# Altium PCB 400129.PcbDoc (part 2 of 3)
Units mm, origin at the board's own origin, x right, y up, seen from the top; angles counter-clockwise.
Board outline 295.85 x 54.86 mm, 2 copper layers (Top Layer, Bottom Layer), stack 1.671 mm thick; 222 components, 127 nets, 693 pads, 1827 vias.
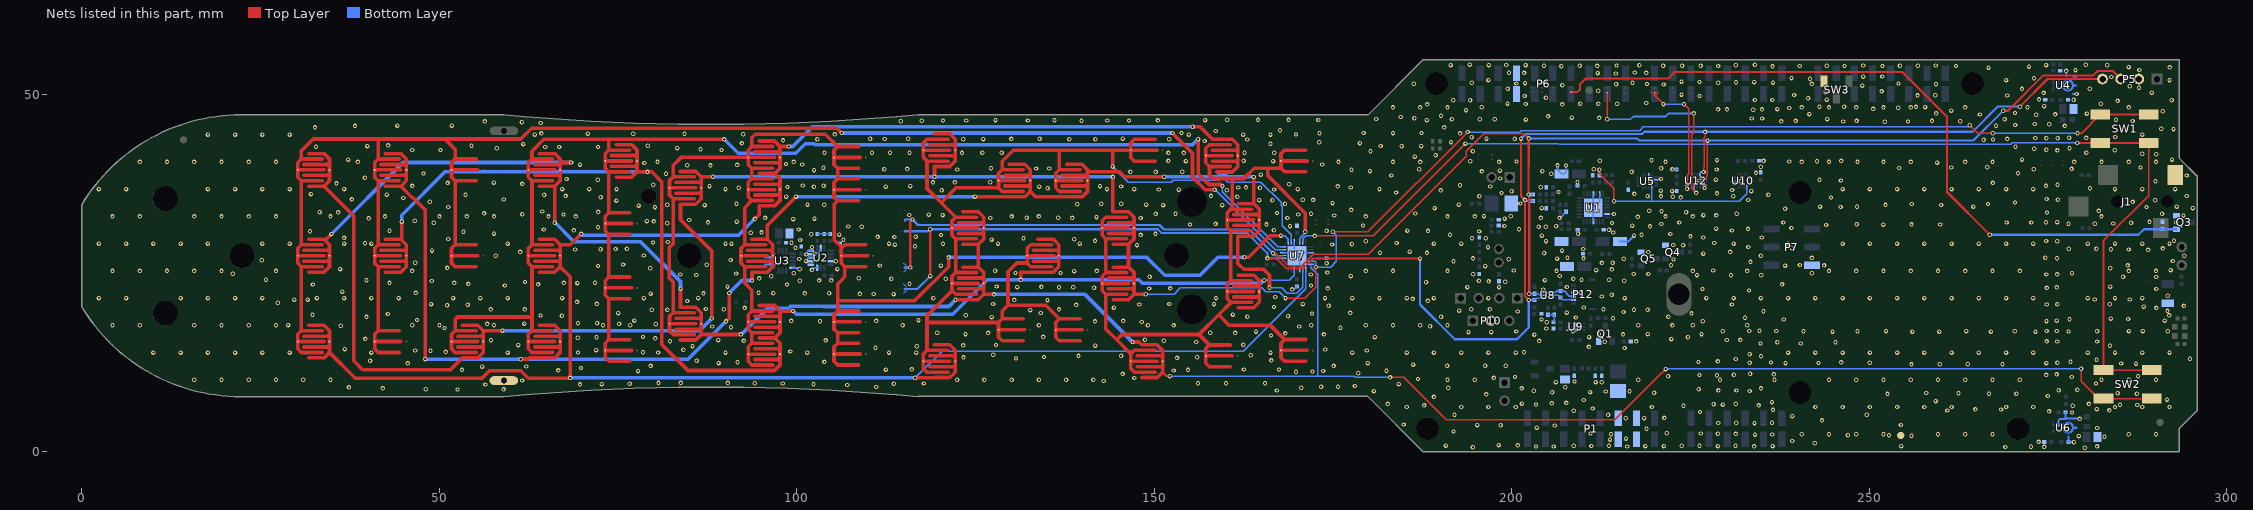
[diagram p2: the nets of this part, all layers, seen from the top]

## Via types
v1: diameter 0.61, hole 0.305, Top Layer to Bottom Layer, tented both sides, 1823 vias
v2: diameter 0.6, hole 0.3, Top Layer to Bottom Layer, tented both sides, 4 vias

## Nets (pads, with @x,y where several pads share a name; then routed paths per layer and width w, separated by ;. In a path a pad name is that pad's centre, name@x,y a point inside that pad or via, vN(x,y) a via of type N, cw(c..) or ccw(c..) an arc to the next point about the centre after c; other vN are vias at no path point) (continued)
D7: SB6.1 U12.13 | length 17.7
  Top Layer w0.203: SB6.1@219.96,50.252 219.96,50.077 219.96,49.885 v1(221.216,48.629) ; v1(224.079,48.606) 224.715,47.971 224.715,38.866 224.511,38.663 v1(224.511,36.805)
  Bottom Layer w0.203: v1(221.216,48.629) 221.239,48.606 v1(224.079,48.606) ; U12.13@224.491,37.305 224.511,37.284 v1(224.511,36.805)
D9: SB9.1 U12.11 | length 28.6
  Top Layer w0.203: v1(225.431,47.343) 225.431,44.663 225.161,44.393 225.161,36.84 v1(225.778,36.223)
  Top Layer w0.254: v1(213.346,46.517) SB9.1@213.346,50.252
  Bottom Layer w0.203: U12.11@225.516,37.08 225.516,36.486 v1(225.778,36.223)
  Bottom Layer w0.254: v1(213.346,46.517) 213.356,46.507 216.59,46.507 216.968,46.886 221.477,46.886 221.934,47.343 v1(225.431,47.343)
GND: Bat2.1 C1.2 C2.1 C3.1 C4.1 C5.1 C6.1 C7.2 C8.1 C9.1 C13.1 C14.1 C15.1 C18.1 C19.2 C20.2 C21.2 C22.2 C23.1 C24.1 C25.1 C26.1 C27.1 C28.1 C29.1 C30.1 C31.1 C32.1 C33.1 C34.1 C35.1 C36.1 C37.1 C39.1 C40.1 C41.1 C42.1 C43.1 C44.1 C45.1 C46.1 C47.1 C48.1 C50.1 C51.1 C52.1 C53.1 C54.1 C55.1 C56.1 J1.1 P1.6 P1.7 P5.2 P6.7 P7.6 P10.2 P12.3 Q1.2 Q3.2 Q4.2 Q5.2 R1.1 R8.1 R17.1 R31.1 R32.2 SW3.1 TP1.1 U1.4 U1.6 U1.13 U1.18 U1.29 U2.4 U2.8 U2.9 U2.10 U2.11 U2.12 U2.13 U2.15 U3.5 U3.10 U3.12 U4.5 U5.3 U5.6 U6.2 U6.5 U7.3 U7.10 U7.17 U7.26 U7.29 U8.4 U9.1 U9.7 U10.6 U12.6 | length 49.5
  Bottom Layer w0.203: U5.3@219.136,38.68 219.136,38.059 v1(219.352,37.844)
  Bottom Layer w0.229: v1(101.316,26.682) 101.316,26.785 101.672,27.141 U2.11@101.956,27.141 ; v1(101.346,27.602) 101.346,27.821 101.666,28.141 102.131,28.141 102.131,28.608 v1(102.138,28.614) ; v1@102.268,25.606 102.403,25.741 102.812,25.741 102.812,25.872 U2.8@102.856,25.916 ; v1(102.489,27.711) 102.489,27.721 102.592,27.824 103.029,27.824 103.356,28.152 U2.15@103.356,28.366 ; C34.1@102.856,30.485 C30.1@103.851,30.485 104.694,30.485 C31.1@104.697,30.483 ; U7.26@168.032,27.861 169.557,27.861 U7.29@169.957,27.461 ; v1(169.291,22.721) 169.551,22.721 C47.1@169.96,23.129 ; U7.29@169.557,28.011 U7.3@169.557,29.386 ; U7.17@170.357,25.536 170.357,27.061 U7.29@169.957,27.461 ; U7.10@171.882,27.861 170.357,27.861 U7.29@169.957,27.461 ; v1(204.394,22.714) 204.402,22.705 U8.4@204.402,22.316 ; C50.1@205.052,19.163 C51.1@205.955,19.163 205.955,18.244 C54.1@205.812,18.101 ; v1(206.381,40.069) 206.381,39.451 C19.2@206.941,38.891 207.351,38.891 207.583,39.124 v1(207.583,40.059) ; v1(206.684,32.722) 206.73,32.722 206.773,32.765 206.81,32.765 207.225,33.179 207.225,33.278 207.526,33.579 R8.1@207.577,33.579 ; U9.1@208.027,17.003 208.422,17.003 v1(208.559,16.866) 208.967,17.273 U9.7@208.967,17.503 ; P12.3@208.648,22.275 209.603,22.275 v1(209.607,22.271) ; v1(209.186,37.703) 209.188,37.701 209.188,37.694 209.187,37.693 C23.1@209.187,37.234 ; C27.1@209.212,31.083 209.212,30.567 v1(209.262,30.518) ; U1.18@211.4,32.234 U1.29@211.4,34.159 ; U1.4@211.4,36.084 U1.29@211.4,34.159 ; U1.6@212.3,36.084 212.3,35.059 v2(211.95,34.709) U1.29@211.4,34.159 ; 277.836,2.159 277.838,2.157 C42.1@277.838,1.388 277.87,1.355 v1(278.59,1.355)
  Bottom Layer w0.254: v1(226.198,37.941) 226.362,38.105 U12.6@226.941,38.105 ; U6.2@276.413,3.836 276.413,4.377 276.641,4.604 277.438,4.604 ; 277.524,52.478 v1(277.524,53.285) ; 278.463,50.038 v1@278.93,50.038 ; 278.463,52.472 278.994,52.472 278.999,52.476
  Bottom Layer w0.3: 95.545,27.221 U3.12@96.599,27.221 ; 95.58,26.221 U3.10@96.599,26.221 ; U3.5@99.399,25.721 100.247,25.721 v1(100.414,25.554) ; C20.2@215.114,29.433 216.26,29.433 v1(217.073,30.247) ; v1(219.352,37.844) 219.562,38.055 U5.6@220.161,38.055 ; v1(222.456,39.508) 222.459,39.505 C52.1@223.065,39.505 ; U10.6@231.049,37.705 231.834,37.705 v1(232.003,37.874) ; C45.1@277.438,5.533 277.438,4.604 277.444,4.597 277.503,4.656 279.111,4.656 ; U4.5@278.46,51.253 278.85,51.253 ; U6.5@278.463,3.386 278.943,3.386
  other v1: 280.121,0.591 194.551,0.638 269.012,0.679 274.444,0.702 272.607,0.713 203.378,0.747 205.842,0.747 216.129,0.747 233.904,0.772 281.838,0.772 218.669,0.803 221.259,0.803 228.813,0.803 236.467,0.803 254.465,0.803 211.125,0.823 208.661,0.849 213.589,0.849 223.768,0.849 226.232,0.853 231.27,0.849 190.778,0.877 200.838,0.905 198.148,0.943 242.37,1.219 273.66,1.396 239.217,1.524 213.734,1.724 215.954,1.86 282.872,2.117 279.273,2.207 255.89,2.263 252.735,2.321 246.99,2.337 234.01,2.413 236.423,2.43 213.869,2.459 240.539,2.459 244.349,2.459 248.159,2.459 251.969,2.459 259.589,2.459 263.399,2.459 267.209,2.459 286.259,2.459 290.069,2.459 231.307,2.515 228.813,2.54 211.008,2.565 226.416,2.565 221.668,2.619 191.844,2.849 218.83,3.247 281.873,3.347 203.475,3.402 205.991,3.687 198.434,3.719 195.153,3.745 254.407,3.761 184.861,3.835 233.934,4.022 228.875,4.039 231.369,4.064 236.372,4.064 243.364,4.409 279.416,4.611 215.925,4.708 218.506,4.723 221.331,4.756 239.214,5.006 191.99,5.192 213.459,5.198 249.631,5.195 278.336,5.519 226.31,5.589 275.137,5.66 208.648,5.747 260.912,5.793 283.556,5.81 236.518,5.872 268.422,5.929 264.822,5.943 281.788,5.979 211.298,6.075 185.294,6.269 192.914,6.269 196.724,6.269 200.534,6.269 219.584,6.269 242.444,6.269 246.254,6.269 250.064,6.269 253.874,6.269 257.684,6.269 261.494,6.269 269.114,6.269 272.924,6.269 284.354,6.269 288.164,6.269 291.974,6.269 278.441,6.446 223.995,6.457 187.731,6.499 234.512,6.511 287.452,6.553 285.039,6.589 229.514,6.613 203.378,6.633 228.219,6.671 182.637,6.709 231.307,6.725 280.693,6.709 201.404,6.755 205.588,6.787 207.625,6.849 236.372,6.965 259.257,7.096 210.053,7.257 291.617,7.315 189.103,7.696 274.959,7.808 196.424,8.037 252.527,8.107 266.725,8.128 270.561,8.128 287.401,8.137 262.458,8.198 284.709,8.201 257.962,8.243 219.898,8.279 205.631,8.35 210.947,8.362 213.131,8.443 216.446,8.47 180.709,8.504 233.249,8.516 203.065,8.561 167.144,8.594 228.882,8.598 231.401,8.581 276.456,8.614 279.086,8.682 52.564,8.73 48.113,8.756 59.004,8.746 226.12,8.756 42.108,8.881 201.361,8.881 234.851,8.881 191.11,8.961 170.56,8.964 37.371,9.02 207.467,9.053 111.121,9.078 173.33,9.119 175.692,9.119 178.048,9.22 107.052,9.349 56.464,9.42 69.698,9.445 102.352,9.46 72.72,9.476 184.18,9.485 76.624,9.535 113.589,9.535 98.055,9.566 117.784,9.561 281.686,9.566 94.117,9.612 156.108,9.612 160.02,9.612 165.481,9.612 80.661,9.655 83.775,9.655 90.358,9.655 212.573,9.745 206.145,9.759 211.709,9.764 208.763,9.84 142.926,9.916 61.595,9.994 15.749,10.079 19.559,10.079 23.369,10.079 27.179,10.079 30.989,10.079 34.799,10.079 122.429,10.079 126.239,10.079 130.049,10.079 133.859,10.079 137.669,10.079 141.479,10.079 191.009,10.079 194.819,10.079 217.679,10.079 229.109,10.079 236.729,10.079 244.349,10.079 248.159,10.079 251.969,10.079 255.779,10.079 259.589,10.079 263.399,10.079 267.209,10.079 271.019,10.079 282.449,10.079 286.259,10.079 290.069,10.079 186.868,10.2 147.222,10.33 197.488,10.356 200.45,10.465 278.303,10.465 221.851,10.583 287.553,10.566 228.697,10.728 226.241,10.744 274.729,10.775 231.051,10.791 276.187,10.839 236.636,10.845 145.567,10.903 233.315,10.931 178.511,11.006 169.816,11.201 172.131,11.236 77.811,11.292 173.609,11.307 182.474,11.354 66.672,11.396 152.705,11.39 53.188,11.467 154.711,11.467 112.471,11.505 162.535,11.517 167.445,11.517 116.095,11.542 69.825,11.734 56.015,11.929 62.186,11.938 79.561,12.025 175.082,12.025 190.95,12.052 196.262,12.052 199.157,12.052 186.195,12.2 255.88,12.243 259.842,12.268 263.754,12.268 268.605,12.268 285.198,12.362 287.274,12.35 45.593,12.378 238.275,12.411 89.078,12.422 179.85,12.416 242.888,12.429 274.749,12.422 233.249,12.463 250.038,12.471 276.29,12.471 236.248,12.505 91.719,12.534 246.075,12.522 103.871,12.583 226.097,12.574 278.114,12.601 228.813,12.652 40.335,12.742 86.004,12.736 166.374,12.793 281.762,12.878 231.307,12.996 294.827,13.029 130.658,13.066 153.187,13.142 123.317,13.218 156.007,13.237 134.569,13.269 234.84,13.374 139.395,13.422 145.357,13.447 163.5,13.523 127.483,13.574 233.249,13.65 10.034,13.889 13.844,13.889 17.654,13.889 21.464,13.889 25.274,13.889 29.084,13.889 40.514,13.889 59.564,13.889 69.41,13.908 80.619,13.908 90.044,13.889 101.474,13.889 112.904,13.889 116.714,13.889 166.244,13.889 177.674,13.889 185.294,13.889 189.104,13.889 192.914,13.889 196.724,13.889 200.534,13.889 238.634,13.889 242.444,13.889 246.254,13.889 250.064,13.889 253.874,13.889 257.684,13.889 261.494,13.889 265.304,13.889 269.114,13.889 272.924,13.889 280.544,13.889 284.354,13.889 288.164,13.889 291.974,13.889 78.511,13.932 201.708,13.946 50.927,13.987 99.111,14.031 48.793,14.133 46.66,14.184 179.705,14.184 71.958,14.234 84.15,14.294 173.912,14.322 36.805,14.379 215.765,14.537 111.019,14.565 210.773,14.688 116.781,14.768 85.419,14.797 283.637,14.839 141.732,14.863 123.292,14.893 61.063,14.935 127.867,14.956 162.458,14.983 234.78,15.164 240.4,15.164 237.135,15.33 245.263,15.329 155.88,15.367 212.98,15.415 276.276,15.432 281.838,15.432 217.392,15.459 274.787,15.457 82.271,15.479 92.608,15.525 203.829,15.525 151.331,15.555 57.252,15.606 104.034,15.594 89.027,15.631 230.062,15.65 231.962,15.661 148.683,15.684 222.315,15.775 39.675,15.809 80.209,15.88 69.369,15.96 72.006,16.032 224.612,16.039 78.495,16.066 180.819,16.055 210.8,16.053 134.468,16.089 166.319,16.277 203.156,16.405 173.721,16.434 212.189,16.448 215.534,16.434 123.596,16.47 219.013,16.47 226.517,16.47 168.334,16.577 126.771,16.647 161.315,16.647 119.659,16.673 157.836,16.673 193.948,16.755 197.113,16.755 164.228,16.817 244.838,16.815 256.007,16.815 259.791,16.815 266.991,16.815 273.221,16.817 200.636,16.84 277.838,16.84 229.505,16.87 240.792,16.866 248.336,16.866 270.332,16.87 281.838,16.866 291.719,16.87 233.211,16.898 236.982,16.898 252.324,16.891 263.55,16.891 274.787,16.898 276.191,16.898 286.289,16.891 288.215,16.891 234.634,16.934 204.82,17.249 50.749,17.333 176.033,17.362 90.805,17.42 88.187,17.533 170.262,17.539 188.57,17.567 36.227,17.636 152.705,17.689 222.456,17.689 4.319,17.699 8.129,17.699 15.749,17.699 19.559,17.699 23.369,17.699 27.179,17.699 46.229,17.699 50.039,17.699 57.659,17.699 72.899,17.699 76.709,17.699 114.809,17.699 133.859,17.699 149.099,17.699 171.959,17.699 179.579,17.699 183.389,17.699 187.199,17.699 191.009,17.699 217.679,17.699 225.299,17.699 232.919,17.699 28.88,17.729 80.273,17.861 56.714,17.907 61.917,17.937 75.162,17.932 69.41,17.983 72.085,17.983 204.88,18.142 148.238,18.171 141.707,18.248 103.257,18.262 226.695,18.263 274.764,18.294 99.238,18.324 111.123,18.324 145.667,18.326 77.292,18.365 276.207,18.364 291.313,18.364 117.023,18.425 46.888,18.445 204.14,18.517 238.032,18.517 277.978,18.562 286.182,18.593 283.743,18.644 214.151,18.68 232.609,18.76 208.955,18.787 127.271,18.851 39.827,18.876 163.017,18.908 190.103,18.898 221.885,18.908 168.719,18.965 67.158,19.035 64.16,19.069 291.941,19.089 123.622,19.107 32.283,19.17 160.985,19.198 42.824,19.286 172.059,19.355 225.131,19.371 75.032,19.405 134.112,19.432 177.409,19.435 207.671,19.477 215.629,19.563 200.838,19.634 235.196,19.656 291.687,19.725 192.634,19.752 132.653,19.824 79.733,19.873 81.907,19.873 218.983,19.88 217.073,19.888 57.201,19.924 61.976,19.924 136.677,19.932 194.335,19.958 196.926,19.945 212.824,19.945 89.786,19.961 87.299,19.985 92.705,20.137 290.129,20.142 144.348,20.178 210.059,20.185 166.731,20.254 288.373,20.32 293.98,20.422 174.372,20.448 51.105,20.508 139.09,20.559 53.975,20.584 147.902,20.619 230.768,20.621 274.803,20.621 48.87,20.666 158.344,20.661 170.753,20.666 276.283,20.65 283.616,20.65 72.028,20.693 127.457,20.686 152.11,20.692 27.432,20.853 69.285,20.984 84.675,21.098 188.252,21.117 135.07,21.221 130.423,21.254 29.722,21.295 31.598,21.295 281.508,21.311 286.397,21.311 186.125,21.395 119.109,21.485 2.414,21.509 6.224,21.509 13.844,21.509 17.654,21.509 21.464,21.509 25.274,21.509 32.894,21.509 36.704,21.509 40.514,21.509 44.324,21.509 51.944,21.509 55.754,21.509 59.564,21.509 67.184,21.509 78.614,21.509 86.234,21.509 158.624,21.509 173.864,21.509 177.674,21.509 181.484,21.509 185.294,21.509 189.104,21.509 196.724,21.509 215.774,21.509 227.204,21.509 231.014,21.509 234.824,21.509 238.634,21.509 242.444,21.509 246.254,21.509 250.064,21.509 253.874,21.509 257.684,21.509 261.494,21.509 265.304,21.509 269.114,21.509 272.924,21.509 280.544,21.509 284.354,21.509 288.164,21.509 166.915,21.663 212.582,21.735 291.718,21.832 213.957,21.977 110.757,22.077 113.553,22.067 108.804,22.098 79.564,22.134 86.97,22.17 96.735,22.193 101.128,22.17 104.522,22.193 46.711,22.235 94.66,22.266 36.449,22.413 233.166,22.573 226.656,22.784 290.128,22.784 149.276,22.845 152.253,22.87 174.255,22.87 274.816,22.932 141.58,22.963 136.677,23.023 138.659,23.023 276.19,23.007 130.835,23.049 193.779,23.049 198.194,23.038 207.695,23.052 134.214,23.074 90.313,23.11 127.949,23.124 283.675,23.11 59.192,23.266 171.915,23.275 32.334,23.404 63.83,23.429 98.646,23.414 237.8,23.429 54.077,23.492 115.763,23.512 69.328,23.607 43.053,23.633 52.095,23.633 67.412,23.632 71.78,23.658 188.01,23.721 62.001,23.759 199.086,23.8 196.749,23.851 48.958,23.904 100.428,23.942 195.394,23.942 215.727,23.945 103.129,23.981 104.816,23.981 39.827,24.013 204.616,24.018 209.739,24.062 213.625,24.065 25.781,24.079 113.236,24.223 120.834,24.215 208.607,24.217 94.755,24.27 108.676,24.281 290.107,24.46 149.351,24.502 285.482,24.491 96.444,24.561 177.461,24.58 206.696,24.597 230.656,24.699 234.89,24.7 225.897,24.723 85.954,24.74 83.718,24.816 171.867,24.815 274.749,24.811 276.27,24.828 194.615,24.848 217.048,24.873 219.099,24.873 21.132,24.906 91.528,24.953 99.574,24.974 241.927,24.975 278.327,24.975 136.89,25.01 130.591,25.022 174.211,25.081 138.811,25.275 141.961,25.309 4.319,25.319 8.129,25.319 11.939,25.319 15.749,25.319 19.559,25.319 27.179,25.319 46.229,25.319 127.737,25.337 179.579,25.319 183.389,25.319 191.009,25.319 206.249,25.319 225.299,25.319 232.919,25.319 244.349,25.319 248.159,25.319 251.969,25.319 255.779,25.319 259.589,25.319 263.399,25.319 267.209,25.319 271.019,25.319 286.259,25.319 290.069,25.319 228.177,25.36 200.269,25.375 211.799,25.42 292.125,25.421 102.115,25.453 213.982,25.526 36.144,25.563 105.68,25.56 79.505,25.69 283.691,25.69 51.14,25.733 196.291,25.975 72.212,25.995 120.138,26.05 238.214,26.046 111.633,26.067 243.666,26.08 286.106,26.08 222.252,26.09 240.28,26.144 87.427,26.162 75.717,26.198 174.092,26.391 212.597,26.432 46.66,26.457 214.089,26.452 233.367,26.571 105.461,26.67 191.844,26.67 292.434,26.7 25.195,26.805 90.752,26.838 169.407,26.911 170.507,26.911 222.605,26.904 199.571,26.95 100.355,26.971 215.656,27.012 206.33,27.028 194.564,27.064 210.024,27.059 276.24,27.082 241.927,27.131 274.604,27.143 207.789,27.157 57.912,27.432 234.823,27.432 294.027,27.432 78.614,27.461 226.788,27.734 204.507,27.784 188.127,27.834 181.56,27.861 219.086,27.951 61.341,27.976 230.533,27.976 169.407,28.011 170.507,28.011 185.719,28.011 48.997,28.154 207.012,28.142 289.001,28.245 69.037,28.297 286.25,28.296 72.568,28.331 74.672,28.366 283.784,28.346 209.973,28.37 76.251,28.408 277.874,28.397 281.748,28.397 291.036,28.464 239.152,28.499 99.824,28.546 196.672,28.643 233.074,28.661 116.544,28.758 223.947,28.895 147.574,28.911 222.564,28.939 113.71,28.991 174.866,29.005 177.628,29.045 120.447,29.102 2.414,29.129 6.224,29.129 10.034,29.129 13.844,29.129 17.654,29.129 25.274,29.129 29.084,29.129 36.704,29.129 40.514,29.129 59.564,29.129 90.044,29.129 90.881,29.128 112.904,29.129 128.144,29.129 139.574,29.129 189.104,29.129 192.914,29.129 231.014,29.129 238.634,29.129 246.254,29.129 250.064,29.129 253.874,29.129 257.684,29.129 261.494,29.129 265.304,29.129 269.114,29.129 272.924,29.129 280.544,29.129 284.354,29.129 288.164,29.129 291.974,29.129 39.624,29.167 183.888,29.221 228.306,29.208 99.276,29.258 79.897,29.288 81.966,29.347 179.563,29.457 276.265,29.457 204.778,29.481 274.717,29.496 141.707,29.513 292.599,29.538 100.47,29.627 106.536,29.678 127.25,29.69 138.811,29.73 51.257,29.779 131.705,29.88 194.437,29.866 196.342,29.87 36.703,29.932 226.776,29.986 234.953,29.986 113.649,30.059 111.304,30.072 116.628,30.096 224.977,30.137 204.174,30.247 120.174,30.333 148.084,30.349 218.124,30.355 105.94,30.389 191.354,30.378 102.022,30.44 150.17,30.485 222.17,30.477 57.658,30.529 93.574,30.643 95.074,30.693 214.173,30.68 53.391,30.784 195.428,30.821 31.928,30.846 43.053,30.917 174.092,30.917 188.276,30.908 185.391,30.945 68.811,30.973 230.768,30.958 166.728,30.998 213.608,31.064 64.643,31.097 100.258,31.1 200.998,31.139 233.031,31.183 228.578,31.228 239.09,31.318 72.217,31.405 109.093,31.483 203.744,31.483 204.751,31.483 107.198,31.519 219.316,31.531 206.188,31.559 168.986,31.576 198.956,31.589 179.188,31.66 216.835,31.646 243.942,31.725 251.943,31.785 154.986,31.798 165.684,31.817 255.89,31.817 259.918,31.801 248.209,31.829 158.58,31.884 220.9,31.873 277.851,31.902 281.508,31.899 284.103,31.932 81.89,31.987 213.998,32.008 49.251,32.04 286.595,32.037 87.584,32.1 223.423,32.075 237.967,32.08 269.193,32.08 272.656,32.075 274.69,32.109 276.276,32.131 292.917,32.131 289.173,32.166 91.599,32.205 80.025,32.241 79.017,32.273 46.584,32.319 84.975,32.423 99.517,32.548 102.483,32.624 198.984,32.624 40.157,32.649 127.061,32.708 148.084,32.702 168.614,32.708 95.58,32.729 136.569,32.732 138.539,32.727 204.03,32.729 132.152,32.747 141.927,32.836 217.606,32.867 4.319,32.939 8.129,32.939 15.749,32.939 19.559,32.939 23.369,32.939 27.179,32.939 34.799,32.939 42.419,32.939 50.039,32.939 53.849,32.939 57.659,32.939 65.279,32.939 69.089,32.939 130.049,32.939 133.859,32.939 179.579,32.939 191.009,32.939 194.819,32.939 199.852,32.944 221.489,32.939 225.299,32.939 282.449,32.939 196.105,32.976 175.156,33.061 293.915,33.043 228.6,33.075 120.405,33.113 226.788,33.111 115.73,33.124 118.469,33.18 170.126,33.189 67.392,33.203 61.634,33.234 214.272,33.259 150.19,33.313 152.972,33.312 171.909,33.313 231.46,33.313 290.94,33.312 56.286,33.355 186.485,33.347 167.157,33.407 35.89,33.488 274.838,33.484 33.274,33.513 224.366,33.524 72.241,33.56 64.423,33.613 220.935,33.655 282.07,33.706 219.218,33.726 177.547,33.84 238.209,33.998 189.198,34.094 204.174,34.091 295.216,34.091 80.18,34.224 51.257,34.243 245.975,34.245 288.743,34.245 248.274,34.281 243.103,34.296 264.536,34.298 292.974,34.298 77.892,34.443 87.122,34.515 151.238,34.515 159.512,34.515 260.033,34.524 81.889,34.549 103.851,34.549 252.243,34.549 101.496,34.577 148.869,34.579 192.569,34.577 139.22,34.644 255.919,34.67 266.582,34.67 91.567,34.707 142.575,34.713 145.372,34.709 168.267,34.714 201.193,34.729 174.911,34.789 270.366,34.874 286.813,34.963 48.692,34.986 74.779,35.139 166.512,35.18 289.975,35.188 164.68,35.209 233.052,35.222 172.204,35.239 170.753,35.251 276.355,35.269 59.036,35.29 37.795,35.316 274.777,35.374 44.982,35.509 244.636,35.574 72.568,35.6 223.632,35.595 161.62,35.672 222.511,35.677 98.522,35.693 220.85,35.732 195.459,35.753 218.983,35.753 230.952,35.756 294.382,35.778 67.68,35.796 157.937,35.799 53.67,35.951 42.672,35.977 64.668,35.966 235.873,35.966 32.055,36.053 217.142,36.082 228.697,36.152 198.555,36.208 183.819,36.271 206.531,36.338 199.974,36.449 233.477,36.463 222.414,36.47 220.828,36.535 190.052,36.575 120.258,36.597 160.124,36.597 230.801,36.632 150.622,36.688 153.425,36.673 166.755,36.688 2.414,36.749 6.224,36.749 17.654,36.749 21.464,36.749 25.274,36.749 29.084,36.749 36.704,36.749 67.184,36.749 70.994,36.749 74.804,36.749 90.044,36.749 143.384,36.749 147.194,36.749 170.054,36.749 181.484,36.749 246.254,36.749 250.064,36.749 253.874,36.749 257.684,36.749 261.494,36.749 265.304,36.749 269.114,36.749 272.924,36.749 284.354,36.749 288.164,36.749 292.78,36.751 135.077,36.866 280.849,36.864 91.884,36.932 164.77,36.932 161.738,36.97 177.479,36.972 162.829,36.992 204.045,37.019 98.704,37.044 102.403,37.087 112.441,37.096 133.909,37.094 145.364,37.117 196.97,37.113 175.652,37.134 87.804,37.171 115.878,37.171 142.409,37.171 46.253,37.196 274.69,37.196 103.759,37.221 100.838,37.247 192.754,37.285 79.942,37.348 276.309,37.368 168.885,37.419 61.634,37.475 35.636,37.552 51.181,37.621 267.264,37.621 57.633,37.653 119.059,37.685 122.084,37.694 127.051,37.711 290.012,37.86 246.016,37.951 72.183,38.06 243.019,38.055 228.52,38.074 67.818,38.161 220.848,38.161 198.376,38.224 39.611,38.35 294.362,38.65 183.155,38.657 164.897,38.771 81.714,38.898 205.522,38.898 47.803,38.924 270.79,38.964 234.152,39.022 146.66,39.177 216.746,39.173 150.19,39.188 153.899,39.188 195.814,39.229 204.274,39.255 180.167,39.268 198.305,39.335 102.412,39.403 177.584,39.452 122.449,39.485 228.64,39.485 112.256,39.514 187.061,39.532 211.445,39.521 272.986,39.524 115.448,39.573 278.273,39.573 133.477,39.634 135.306,39.634 127.169,39.659 220.877,39.66 254.178,39.7 103.737,39.73 261.442,39.776 287.917,39.779 266.485,39.815 234.814,39.876 87.935,40.066 84.684,40.079 91.669,40.142 69.698,40.174 100.779,40.193 173.494,40.193 98.501,40.257 78.7,40.396 259.472,40.455 248.336,40.55 8.129,40.559 11.939,40.559 15.749,40.559 19.559,40.559 23.369,40.559 27.179,40.559 38.609,40.559 80.519,40.559 99.569,40.559 175.769,40.559 183.389,40.559 187.199,40.559 198.22,40.561 221.489,40.559 240.539,40.559 244.349,40.559 251.969,40.559 255.779,40.559 263.399,40.559 267.209,40.559 278.639,40.559 282.449,40.559 286.259,40.559 290.069,40.559 238.782,40.607 194.193,40.633 200.66,40.615 242.667,40.633 166.613,40.658 154.42,40.666 151.972,40.7 235.214,40.7 246.075,40.698 162.49,40.72 212.297,40.719 219.529,40.789 228.681,40.797 37.287,40.879 271.34,40.869 292.307,40.869 186.428,41.288 189.339,41.476 290.107,41.631 288.163,41.699 103.879,41.823 110.531,41.826 113.036,41.824 115.763,41.823 123.115,41.819 151.967,41.819 154.122,41.819 162.623,41.824 166.765,41.826 125.954,41.833 128.645,41.833 280.349,41.845 180.226,42.049 194.551,42.054 276.29,42.159 284.307,42.182 46.228,42.227 50.19,42.215 89.484,42.227 274.749,42.251 86.546,42.33 273.041,42.381 58.039,42.454 83.297,42.479 277.984,42.47 64.829,42.632 66.777,42.632 72.212,42.632 270.44,42.666 32.766,42.682 184.59,42.741 39.954,42.759 187.33,42.759 181.653,42.782 54.525,42.809 79.173,42.809 42.875,42.86 61.773,43.038 166.243,43.104 92.329,43.14 178.748,43.18 173.067,43.309 191.495,43.316 157.034,43.481 98.086,43.561 265.973,43.65 267.287,43.676 163.007,43.687 102.887,43.731 123.292,43.731 138.125,43.716 141.757,43.717 152.094,43.718 126.086,43.739 110.261,43.779 112.319,43.764 130.021,43.775 269.277,43.775 115.595,43.79 133.96,43.785 200.391,43.79 145.593,43.815 196.459,43.81 274.749,43.872 276.316,43.872 273.186,43.891 277.928,43.922 280.332,43.913 194.376,43.99 284.378,44.044 17.654,44.369 21.464,44.369 25.274,44.369 29.084,44.369 63.374,44.369 154.814,44.369 162.434,44.369 166.244,44.369 169.816,44.385 288.164,44.369 92.514,44.41 105.32,44.399 77.149,44.486 84.308,44.486 70.775,44.511 64.287,44.537 192.794,44.544 173.11,44.568 153.809,44.587 183.389,44.581 187.37,44.587 179.272,44.601 158.593,44.867 167.582,44.982 292.52,45.134 290.82,45.179 32.629,45.384 190.539,45.385 38.22,45.592 267.697,45.604 277.333,45.592 44.16,45.627 51.766,45.627 270.383,45.706 275.159,45.808 273.127,45.858 64.211,45.984 61.57,46.086 252.138,46.161 56.366,46.214 237.676,46.218 246.334,46.201 255.407,46.203 114.554,46.246 262.709,46.229 239.679,46.285 248.209,46.286 258.751,46.29 286.806,46.279 117.481,46.319 139.811,46.319 120.447,46.34 123.697,46.336 132.328,46.335 143.424,46.34 146.463,46.335 136.045,46.373 150.504,46.358 157.103,46.394 127.787,46.4 164.506,46.423 168.767,46.423 172.945,46.408 188.098,46.402 160.201,46.444 201.966,46.471 284.48,46.452 191.618,46.513 195.516,46.517 197.619,46.517 268.91,46.513 181.047,46.551 244.096,46.535 233.553,46.621 234.998,46.621 186.377,46.645 212.216,46.708 208.379,46.744 184.468,46.839 205.078,46.922 190.086,47.016 273.33,47.155 265.449,47.18 275.975,47.201 241.605,47.23 280.415,47.31 259.359,47.343 270.353,47.396 291.029,47.633 261.442,47.72 193.58,47.796 233.757,47.841 228.844,47.903 230.093,47.903 234.981,47.903 237.135,47.936 250.546,47.968 238.793,48.087 254.025,48.121 183.389,48.179 187.199,48.179 191.009,48.179 195.801,48.188 240.539,48.179 244.349,48.179 248.159,48.179 251.969,48.179 255.779,48.179 263.399,48.179 272.109,48.188 286.259,48.179 257.788,48.22 256.515,48.243 243.019,48.263 246.463,48.278 274.444,48.351 188.177,48.591 207.043,48.594 201.927,48.658 214.738,48.673 282.365,48.678 199.388,48.701 209.589,48.689 212.105,48.696 218.806,48.781 284.709,49.084 191.813,49.167 194.168,49.186 292.265,49.171 233.987,49.216 236.436,49.216 244.031,49.264 278.562,49.255 273.721,49.292 241.43,49.458 204.762,49.523 201.791,49.775 226.241,49.764 256.728,49.853 269.265,49.845 259.211,49.871 239.467,49.901 223.721,49.958 278.974,50.049 274.359,50.203 289.484,50.241 243.792,50.313 246.569,50.364 251.714,50.416 212.085,50.505 271.348,50.769 199.412,50.785 280.816,50.791 287.705,50.935 286.397,51.132 248.993,51.22 207.068,51.277 221.226,51.387 214.581,51.414 259.311,51.414 218.898,51.448 241.943,51.468 186.279,51.492 200.635,51.521 254.069,51.508 201.848,51.567 194.399,51.619 216.882,51.624 228.854,51.624 236.518,51.638 231.343,51.697 204.603,51.726 226.241,51.726 233.904,51.715 223.727,51.776 196.724,51.989 269.114,51.989 291.974,51.989 241.693,52.172 273.009,52.263 239.099,52.273 283.82,52.432 249.149,52.476 251.816,52.502 214.542,52.916 211.989,52.968 201.721,52.998 218.786,52.998 199.608,53.019 217.192,53.055 278.83,53.386 287.759,53.412 266.653,53.742 292.014,53.766 286.25,53.809 272.313,53.884 236.447,53.914 206.934,53.935 228.848,53.96 240.253,53.962 246.517,53.96 251.825,53.967 262.119,53.96 204.495,53.994 211.938,53.985 221.158,53.994 226.394,53.989 254.264,53.993 256.773,53.993 209.474,54.011 223.808,54.011 244.031,54.005 214.63,54.036 249.141,54.039 259.272,54.039 217.83,54.062 231.307,54.062 191.44,54.087 196.774,54.087 201.93,54.087 274.713,54.087 283.261,54.077 199.212,54.112 233.985,54.135 280.264,54.135 194.107,54.155
  other v2: 210.85,33.609 211.95,33.609 210.85,34.709
I2C_CLK: P5.3 R13.1 R28.2 SB19.2 SB20.2 U7.25 U8.3 U12.8 | length 226.8
  Top Layer w0.203: v1(226.941,36.896) 226.941,38.204 227.354,38.618 v1(227.355,43.536) v1(227.355,43.536)
  Top Layer w0.254: v1(166.593,27.789) 167.01,27.789 168.767,26.032 170.609,26.032 172.217,27.64 179.921,27.64 193.63,41.349 193.63,42.013 196.095,44.478 201.722,44.478 v1(202.356,43.843)
  Top Layer w0.305: v1(115.878,25.791) 115.878,32.188 v1(116.184,32.494) ; v1(202.356,43.843) v1(202.34,35.993) 202.439,36.095 v1(202.439,22.105) ; v1(268.708,47.706) 269.381,47.706 274.325,52.65 281.306,52.65 281.915,53.26 284.023,53.26 P5.3@285.143,52.14
  Bottom Layer w0.203: v1(166.593,27.789) 166.918,27.463 168.031,27.463 U7.25@168.032,27.461 ; v1(202.439,22.105) 202.366,22.105 202.361,22.11 R28.2@203.156,22.11 203.688,22.11 203.881,21.916 U8.3@204.402,21.916 ; v1(226.941,36.896) U12.8@226.941,37.305
  Bottom Layer w0.305: SB19.2@115.087,25.775 115.375,25.775 115.862,25.775 v1(115.878,25.791) ; 115.138,32.493 v1@116.185,32.493 ; v1(116.184,32.494) v1@116.185,32.493 ; v1(166.593,27.789) 163.291,31.091 151.349,31.091 150.718,31.721 116.956,31.721 v1@116.185,32.493 ; v1(202.34,35.993) R13.1@202.909,35.993 ; v1(202.356,43.843) 217.523,43.843 217.832,43.534 264.536,43.534 v1(268.708,47.706)
I2C_CLK_TP: P12.4 R30.2 U8.6 | length 3.3
  Bottom Layer w0.203: U8.6@205.702,22.316 206.157,22.316 206.342,22.501 R30.2@206.829,22.501 207.322,22.501 208.048,21.775 P12.4@208.648,21.775
I2C_DATA: P5.4 R11.1 R27.2 SB21.2 SB24.2 U7.24 U8.2 U12.4 | length 234.4
  Top Layer w0.203: v1(226.821,39.143) 226.821,39.807 226.907,39.893 226.907,43.23 226.822,43.315 226.822,43.872 227.026,44.077 v1(227.026,44.748)
  Top Layer w0.254: v1(165.815,27.059) 167.071,27.059 168.503,25.628 170.744,25.628 172.15,27.034 v1(187.155,27.034)
  Top Layer w0.305: v1(118.671,24.58) v1(118.671,31.137) ; v1(201.287,43.815) 201.287,35.78 v1(201.82,35.247) 201.842,35.225 201.842,21.758 v1(202.358,21.241) ; v1(271.033,48.275) 274.898,52.14 P5.4@282.603,52.14
  Bottom Layer w0.203: v1(165.815,27.059) 167.508,27.059 167.511,27.061 U7.24@168.032,27.061 ; R27.2@203.156,21.241 203.431,21.516 U8.2@204.402,21.516 ; U12.4@226.316,38.747 226.316,38.944 226.515,39.143 v1(226.821,39.143)
  Bottom Layer w0.305: SB24.2@115.087,22.795 116.886,22.795 v1(118.671,24.58) ; SB21.2@115.11,30.846 118.376,30.846 118.671,31.142 150.484,31.142 151.036,30.59 163.001,30.59 165.815,27.776 v1(165.815,27.059) ; v1(187.155,27.034) 187.155,20.603 192.003,15.755 200.727,15.755 202.358,17.387 v1(202.358,21.241) R27.2@203.156,21.241 ; v1(201.287,43.815) 201.927,44.455 218.218,44.455 218.535,44.772 264.44,44.772 267.959,48.29 271.018,48.29 v1(271.033,48.275) ; v1(201.82,35.247) 201.978,35.089 R11.1@202.925,35.089
I2C_DATA_TP: P12.5 R29.2 U8.7 | length 3.2
  Bottom Layer w0.203: U8.7@205.702,21.916 206.506,21.916 R29.2@206.827,21.596
  Bottom Layer w0.254: R29.2@206.827,21.596 207.147,21.275 P12.5@208.648,21.275
"I2S SCLK": R15.2 U5.9 U10.1 | length 28
  Top Layer w0.203: v1(212.241,39.452) 212.241,38.906 214.28,36.867 v1(214.28,35.061)
  Bottom Layer w0.203: R15.2@212.241,38.691 v1(212.241,39.452) ; v1(214.28,35.061) 214.28,35.106 214.325,35.061 219.536,35.061 ; U5.9@219.536,37.03 219.536,35.061 ; U10.1@232.874,37.08 232.874,36.117 231.817,35.061 219.536,35.061
IR_LED: Q3.1 R1.2 SB32.1 | length 102.2
  Top Layer w0.305: SB32.1@208.28,50.308 209.166,50.308 209.547,50.688 209.547,51.444 210.325,52.222 221.851,52.222 222.74,53.111 254.635,53.111 260.858,46.888 260.858,36.34 v1(266.843,30.355)
  Bottom Layer w0.305: v1(266.843,30.355) 287.611,30.355 288.404,31.148 Q3.1@292.949,31.148
KEYIN_0: K1.1 K2.1 K3.1 K4.1 K5.1 K6.1 K7.1 K8.1 U7.27 | length 199.7
  Top Layer w0.508: 30.722,16.956 30.722,25.908 ; 30.722,28.956 30.722,37.908 ; 30.722,40.956 30.722,42.083 32.401,43.762 41.459,43.762 ; 41.472,16.956 41.472,25.908 ; 41.472,28.956 41.472,37.908 ; 41.472,40.956 41.472,43.75 41.459,43.762 ; 52.222,28.956 52.222,37.908 ; 52.222,40.956 52.222,42.341 50.801,43.762 ; v1(106.288,44.587) 105.612,45.263 92.231,45.263 92.217,45.25 86.726,45.25 86.712,45.263 62.925,45.263 61.424,43.762 50.801,43.762 ; v1(152.527,44.587) 155.346,41.768 155.346,38.441 157.124,36.663 v1(158.435,36.663) ; 41.459,43.762 50.801,43.762
  Bottom Layer w0.203: v1@158.502,36.663 166.905,28.26 167.091,28.26 167.092,28.261 U7.27@168.032,28.261
  Bottom Layer w0.305: v1(158.435,36.663) v1@158.502,36.663
  Bottom Layer w0.508: v1(106.288,44.587) v1(152.527,44.587)
KEYIN_1: K9.1 K10.1 K11.1 K12.1 K13.1 K14.1 K15.1 K16.1 U7.28 | length 167.3
  Top Layer w0.508: 52.222,16.956 52.222,18.516 52.567,18.862 62.972,18.862 ; 62.972,16.956 62.972,18.862 ; 62.972,25.908 62.972,18.862 ; 62.972,28.956 62.972,37.908 ; 62.972,40.956 62.972,42.061 64.618,43.706 73.709,43.706 ; 73.722,15.706 73.722,21.408 ; 73.722,24.456 73.722,30.408 ; 73.722,33.456 73.722,39.158 ; 73.722,42.206 73.722,43.693 73.709,43.706 ; v1(89.869,43.706) 73.709,43.706 ; v1(156.126,43.712) 156.133,43.704 156.133,38.906 157.64,37.399 159.324,37.399 v1(159.538,37.185)
  Bottom Layer w0.203: v1(159.538,37.185) 159.538,36.357 167.234,28.661 U7.28@168.032,28.661
  Bottom Layer w0.508: v1(89.869,43.706) 91.825,41.75 99.859,41.75 101.188,43.078 102.412,43.078 102.547,42.944 155.358,42.944 v1(156.126,43.712)
KEYIN_2: K17.1 K18.1 K19.1 K20.1 K21.1 K22.1 K23.1 K24.1 K25.1 K26.1 K27.1 K28.1 U7.1 | length 146.3
  Top Layer w0.508: 82.722,19.456 82.722,23.763 82.175,24.311 82.175,28.581 82.722,29.129 82.722,35.408 ; 82.722,38.456 82.722,40.099 83.805,41.182 K17.1@93.214,41.182 ; 92.722,25.908 92.722,23.608 93.722,22.608 93.722,19.706 ; 92.722,28.956 92.722,34.158 93.722,35.158 ; 93.722,15.198 93.722,16.658 ; 93.722,38.206 93.722,39.658 ; 93.722,42.706 93.722,43.95 94.188,44.416 104.006,44.416 105.722,42.701 ; 105.722,15.206 105.722,16.658 ; 105.722,19.706 105.722,23.473 106.722,24.473 106.722,25.908 ; 105.722,21.127 116.467,21.127 121.238,25.898 v1(121.238,27.199) ; 105.722,35.139 105.252,34.669 105.252,29.638 106.214,28.675 106.214,28.448 ; 105.722,38.187 105.722,39.653 ; v1(162.602,27.217) 163.2,27.217 166.23,30.247 v1(167.714,30.247)
  Bottom Layer w0.203: v1(167.714,30.247) 168.246,30.247 168.757,29.735 U7.1@168.757,29.386
  Bottom Layer w0.508: v1(121.238,27.199) 148.963,27.199 151.461,24.701 156.405,24.701 158.921,27.217 v1(162.602,27.217)
KEYIN_3: K29.1 K30.1 K31.1 K32.1 K33.1 K34.1 K35.1 K36.1 K37.1 K38.1 U7.2 | length 117.8
  Top Layer w0.203: 144.176,42.165 144.193,42.182
  Top Layer w0.508: 118.222,14.206 118.222,18.12 ; 118.222,40.669 118.222,36.831 120.202,34.851 ; 121.714,22.541 118.222,19.049 118.222,18.12 ; 122.222,25.081 122.222,29.783 ; 122.222,32.831 120.202,34.851 ; 128.214,18.099 118.244,18.099 118.222,18.12 ; 128.214,36.928 122.278,36.928 120.202,34.851 ; 128.722,18.607 128.722,19.692 129.535,20.505 129.535,25.196 130.755,26.416 132.214,26.416 ; 128.722,39.468 128.722,40.628 130.276,42.182 136.722,42.182 ; 129.535,20.514 134.815,20.514 136.722,18.607 ; 136.722,39.468 136.722,42.182 ; v1(144.176,39.888) 144.176,42.165 ; K38.1@146.714,42.182 144.193,42.182 136.722,42.182
  Bottom Layer w0.203: v1(144.176,39.888) 146.354,37.711 152.38,37.711 152.622,37.953 159.013,37.953 159.159,38.099 159.917,38.099 160.275,37.741 164.92,37.741 167.734,34.927 167.734,34.493 167.917,34.309 167.917,31.621 169.157,30.381 U7.2@169.157,29.386
KEYIN_4: K39.1 K40.1 K41.1 K42.1 K43.1 K44.1 K45.1 K46.1 K47.1 U7.5 | length 83.2
  Top Layer w0.508: K40.1@142.714,23.557 142.714,24.554 143.222,25.062 143.222,25.081 143.222,29.783 ; 143.222,22.033 143.222,17.19 144.743,15.669 ; 146.714,13.698 144.743,15.669 ; 157.722,14.956 156.259,16.419 ; 157.722,39.908 157.722,38.706 158.19,38.238 160.692,38.238 ; 160.722,20.908 160.722,20.882 159.006,19.165 ; 160.722,23.956 160.716,23.962 160.716,30.902 160.722,30.908 ; 160.722,33.956 160.884,34.118 160.884,38.046 160.692,38.238 ; 167.714,39.666 165.849,39.666 ; 168.222,15.718 166.253,17.687 160.484,17.687 159.006,19.165 ; v1(171.12,30.795) 171.12,33.378 165.849,38.648 165.849,39.666 ; 144.743,15.669 145.492,16.419 156.259,16.419 ; 156.259,16.419 159.006,19.165 ; 160.692,38.238 162.557,38.238 163.985,39.666 165.849,39.666
  Bottom Layer w0.203: U7.5@170.357,29.386 170.357,29.908 170.866,30.416 170.871,30.416 171.12,30.665 v1(171.12,30.795)
KEYIN_5: SW1.1 SW2.1 U7.6 | length 165.5
  Top Layer w0.203: v1(172.441,30.211) 180.611,30.211 v1(193.507,43.106) ; SW2.1@282.729,11.435 SW2.1@289.479,11.435
  Top Layer w0.254: v1(279.061,43.206) 279.074,43.193 SW1.1@282.306,43.193 SW1.1@289.056,43.193 289.056,35.85 282.729,29.522 SW2.1@282.729,11.435
  Bottom Layer w0.203: U7.6@170.757,29.386 170.757,29.809 171.16,30.211 v1(172.441,30.211) ; v1(193.507,43.106) 193.509,43.104 206.516,43.104 206.619,43.001 269.779,43.001 269.983,43.206 v1(279.061,43.206)
KEYOUT_0: K1.2 K9.2 K21.2 K32.2 K39.2 K40.2 SW1.2 U7.13 | length 320.6
  Top Layer w0.203: v1(168.351,21.507) 171.069,21.507 172.569,23.008 v1(172.569,25.853) ; v1(174.96,30.782) 179.866,30.782 193.813,44.729 v1(193.816,44.726)
  Top Layer w0.254: v1(264.028,45.677) 265.137,44.568 v1(267.252,44.568) ; v1(279.11,44.556) 279.669,44.556 SW1.2@282.306,47.193 SW1.2@289.056,47.193
  Top Layer w0.508: 33.897,37.146 38.043,33 38.043,12.738 39.29,11.491 51.583,11.491 53.238,13.146 ; 56.159,16.956 58.845,16.956 v1(58.852,16.963) ; 83.738,34.646 83.738,32.479 88.114,28.103 v1(88.114,18.658) ; 86.659,38.456 88.267,38.456 v1(88.291,38.479) ; 119.238,39.907 119.257,39.888 v1(119.257,38.487) ; v1(144.209,38.455) 144.209,33.622 144.238,33.593 ; 146.397,25.843 146.397,29.021 ; 147.159,22.033 v1@148.801,22.033
  Bottom Layer w0.203: v1(148.801,22.033) 152.774,22.033 153.663,22.923 165.051,22.923 165.578,22.396 167.462,22.396 v1(168.351,21.507) ; U7.13@171.882,26.661 172.409,26.661 172.569,26.502 v1(172.569,25.853) 174.647,25.853 175.438,26.644 175.438,30.304 v1(174.96,30.782) ; v1(193.816,44.726) 201.124,44.726 201.341,44.942 217.863,44.942 218.396,45.475 263.826,45.475 v1(264.028,45.677)
  Bottom Layer w0.254: v1(267.252,44.568) 267.264,44.556 v1(279.11,44.556)
  Bottom Layer w0.508: v1(58.852,16.963) 86.418,16.963 v1(88.114,18.658) ; v1(88.291,38.479) 119.249,38.479 v1(119.257,38.487) 144.176,38.487 v1(144.209,38.455)
KEYOUT_1: K2.2 K10.2 K22.2 K29.2 K33.2 K41.2 SW2.2 U7.14 | length 301.3
  Top Layer w0.203: v1(182.978,10.414) 184.897,10.414 190.834,4.477 214.418,4.477 220.418,10.477 v1(221.523,11.582) ; v1(279.603,11.631) 279.603,9.882 282.05,7.435 SW2.2@282.729,7.435 SW2.2@289.479,7.435
  Top Layer w0.305: 151.159,11.158 151.716,10.601 v1(152.153,10.601)
  Top Layer w0.508: 34.03,29.585 34.897,30.451 v1(34.926,30.451) ; v1(66.147,32.055) 66.147,37.146 66.909,37.908 ; 66.909,40.517 66.951,40.475 v1(68.444,40.475) ; 83.738,20.218 v1(83.738,22.836) ; 86.659,16.408 v1@92.199,16.408 ; v1(122.204,21.267) 123.234,21.267 123.238,21.271 ; 125.397,29.021 125.397,25.843 125.53,25.71 ; 126.159,22.033 127.578,22.033 v1(127.587,22.024) ; v1(146.954,15.367) 147.839,15.367 148.238,14.968
  Bottom Layer w0.203: v1@152.196,10.558 172.858,10.558 ; U7.14@171.882,26.261 171.882,25.785 172.858,24.81 172.858,10.558 ; v1(182.978,10.414) 178.084,10.414 177.94,10.558 172.858,10.558 ; v1(221.523,11.582) 221.572,11.631 v1(279.603,11.631)
  Bottom Layer w0.305: v1(152.153,10.601) v1@152.196,10.558
  Bottom Layer w0.508: v1(34.926,30.451) 44.95,40.475 v1(68.444,40.475) ; v1(66.147,32.055) 66.147,32.098 68.841,29.404 78.16,29.404 83.738,23.826 v1(83.738,22.836) ; v1(92.165,16.434) 92.276,16.434 95.903,20.06 98.87,20.06 99.202,20.392 103.76,20.392 103.811,20.341 121.278,20.341 v1(122.204,21.267) ; v1(127.587,22.024) 140.297,22.024 v1(146.954,15.367)
KEYOUT_2: K3.2 K11.2 K17.2 K23.2 K34.2 K42.2 U7.15 | length 259.5
  Top Layer w0.508: 34.659,13.908 38.27,10.297 55.982,10.297 57.024,11.34 61.406,11.34 62.448,10.297 68.319,10.297 68.319,24.498 66.909,25.908 ; 66.909,28.956 68.325,28.956 v1(69.854,30.485) ; v1(94.143,32.585) 94.738,33.18 94.738,34.396 ; 97.659,42.706 97.662,42.709 v1(98.875,42.709) ; v1(116.58,10.374) 116.58,10.387 116.575,10.393 119.235,10.393 119.238,10.396 ; v1(155.36,45.467) 155.373,45.454 156.392,45.454 158.128,43.718 158.738,43.718
  Bottom Layer w0.203: v1(116.58,10.374) 120.314,14.107 162.438,14.107 171.157,22.827 U7.15@171.157,25.536
  Bottom Layer w0.508: v1(68.319,10.348) 116.554,10.348 v1(116.58,10.374) ; v1(69.854,30.485) 70.063,30.276 91.834,30.276 v1(94.143,32.585) ; v1(98.875,42.709) 99.431,42.709 102.189,45.467 v1(155.36,45.467)
KEYOUT_3: K4.2 K12.2 K24.2 K30.2 K35.2 K43.2 U7.16 | length 170.7
  Top Layer w0.508: 44.647,37.146 46.176,35.617 46.253,35.617 48.046,33.824 v1(48.046,12.978) ; v1(61.416,12.948) 62.403,12.948 62.601,13.146 63.988,13.146 ; v1(90.117,18.257) 90.555,18.695 v1(90.555,22.222) ; 93.738,25.146 93.74,25.144 v1(93.74,23.974) ; 95.897,29.718 95.897,31.681 v1(99.909,35.693) ; v1(124.916,35.693) 124.951,35.658 129.738,35.658 ; 132.659,36.42 133.421,35.658 137.738,35.658 ; 140.659,39.468 140.948,39.179 144.47,39.179 144.475,39.184 145.149,39.184 145.867,38.465 v1(151.388,38.465) ; 161.69,30.146 161.69,26.35 162.519,25.522 165.285,25.522 166.116,24.691 v1(166.116,22.963) ; 163.897,34.718 163.897,38.426 v1(163.914,38.443)
  Bottom Layer w0.203: v1(166.116,22.963) 167.831,22.963 168.62,22.175 169.933,22.175 170.753,22.995 170.753,25.532 U7.16@170.757,25.536
  Bottom Layer w0.508: v1(48.046,12.978) 61.386,12.978 v1(61.416,12.948) 84.808,12.948 v1(90.117,18.257) ; v1(90.555,22.222) 92.308,23.974 v1(93.74,23.974) ; v1(99.909,35.693) v1(124.916,35.693) ; v1(151.388,38.465) 151.391,38.468 158.846,38.468 158.959,38.582 160.116,38.582 160.233,38.465 163.818,38.465 163.855,38.502 v1(163.914,38.443)
KEYOUT_4: K5.2 K13.2 K18.2 K25.2 K36.2 K44.2 U7.19 | length 162.2
  Top Layer w0.203: 164.659,23.956 164.791,24.088 164.866,24.013 v1(165.379,24.013)
  Top Layer w0.508: v1(44.762,32.205) 44.78,32.186 44.78,29.585 ; 77.659,39.158 79.726,39.158 81.102,37.782 81.102,15.067 84.781,11.388 94.738,11.388 ; 97.659,19.706 v1(99.486,19.706) ; v1(131.323,24.053) 131.323,25.146 133.738,25.146
  Bottom Layer w0.203: v1(165.379,24.013) v1@165.4,23.993 ; v1@165.458,24.092 165.56,23.99 168.838,23.99 169.557,24.71 U7.19@169.557,25.536
  Bottom Layer w0.508: v1(44.762,32.205) 44.762,33.109 50.813,39.16 v1(79.126,39.16) ; v1(99.486,19.706) 99.927,19.265 121.802,19.265 126.625,24.088 147.82,24.088 148.302,23.607 164.973,23.607 165.359,23.993 v1@165.4,23.993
